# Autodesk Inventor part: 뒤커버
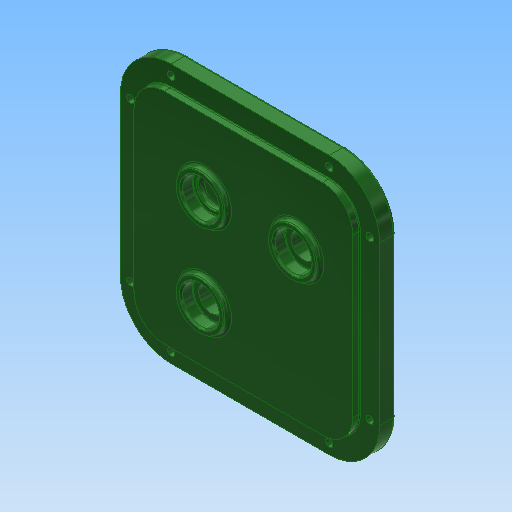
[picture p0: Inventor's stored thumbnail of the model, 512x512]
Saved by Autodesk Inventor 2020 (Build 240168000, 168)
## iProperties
Created: 2016-12
Part Number: 뒤커버
Material: 알루미늄 6061
Document SubType Name: Modeling
Designer: mduedu
Density: 2.71 g/cm^3
Mass: 786.928 g
Surface Area: 577.134 cm^2
Volume: 290.379 cm^3
Appearance: 매끄러움 - 짙은 산림 녹색
Author: mduedu
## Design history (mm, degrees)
sketch "스케치1"
  geometry: L1 (-54, 50)-(-54, -44); L2 (-24, 80)-(70, 80); L3 (100, 50)-(100, -44); L4 (70, -74)-(-24, -74); A1 r 30 centre (-24, -44) between (-54, -44) and (-24, -74); A2 r 30 centre (70, 50) between (100, 50) and (70, 80); A3 r 30 centre (70, -44) between (70, -74) and (100, -44); A4 r 30 centre (-24, 50) between (-24, 80) and (-54, 50); 1 further point
  constraints: 8 end point, 8 point on circle, 8 tangent, 4 centre point, 3 equal radius, 3 perpendicular, 1 horizontal, 1 vertical
  dimensions: "d80" = 30 radius of A2; "d81" = 154 distance between parallel lines of L4 L2; "d82" = 100 distance from line of L3 point (0, 0); "d115" = 80 distance from line of L2 point (0, 0)
extrude "돌출1" new body sketch "스케치1" distance "d3" = 14; taper "d4" = 0 deg
sketch "스케치2"
  geometry: C1 r 14 at (0, 26); 1 further point
  constraints: 1 centre point, 1 vertical alignment
  dimensions: "d5" = 28 diameter of C1; "d6" = 26 distance of C1.centre point (0, 0)
extrude "돌출2" join sketch "스케치2" distance "d7" = 3; taper "d8" = 0 deg
sketch "스케치3"
  geometry: C1 r 14 at (0, -28.87); C2 r 14 at (0, 26) reference; C3 r 14 at (54.87, 26); 1 further point
  constraints: 2 centre point, 1 horizontal alignment, 1 vertical alignment
  dimensions: "d9" = 28 diameter of C1; "d69" = 54.87 distance of C1.centre C2.centre; "d83" = 28 diameter of C3; "d84" = 54.87 distance of C3.centre C2.centre
extrude "돌출3" join sketch "스케치3" distance "d11" = 3; taper "d12" = 0 deg
hole "구멍1" diameter "d15" = 22; stored, may be unused: countersink angle "d19" = 90 deg, drill point angle "d21" = 0 deg; dims "d13" = 10, "d14" = 10, "d16" = 6, "d17" = 4, "d18" = 2, "d20" = 7
hole "구멍2" diameter "d24" = 18; stored, may be unused: countersink angle "d28" = 90 deg, drill point angle "d30" = 0 deg; dims "d25" = 6, "d26" = 4, "d27" = 2, "d29" = 3, "d119" = 10, "d120" = 10
hole "구멍3" diameter "d33" = 22; stored, may be unused: countersink angle "d37" = 90 deg, drill point angle "d39" = 0 deg; dims "d31" = 10, "d32" = 10, "d34" = 6, "d35" = 4, "d36" = 2, "d38" = 7
hole "구멍7" diameter "d87" = 22; stored, may be unused: countersink angle "d91" = 90 deg, drill point angle "d93" = 0 deg; dims "d85" = 10, "d86" = 10, "d88" = 6, "d89" = 4, "d90" = 2, "d92" = 7
sketch "스케치4"
  geometry: C1 r 14 at (0, -28.87) reference; C2 r 18 at (0, -28.87); C3 r 14 at (-54.87, 26) reference; C4 r 18 at (-54.87, 26); 1 further point
  constraints: 2 centre point, 2 coincident
  dimensions: "d40" = 36 diameter of C2; "d94" = 36 diameter of C4
extrude "돌출4" join sketch "스케치4" distance "d41" = 4; taper "d42" = 0 deg
hole "구멍4" diameter "d45" = 22; stored, may be unused: countersink angle "d49" = 90 deg, drill point angle "d51" = 0 deg; dims "d43" = 10, "d44" = 10, "d46" = 6, "d47" = 4, "d48" = 2, "d50" = 7
hole "구멍8" diameter "d97" = 22; stored, may be unused: countersink angle "d101" = 90 deg, drill point angle "d103" = 0 deg; dims "d95" = 10, "d96" = 10, "d98" = 6, "d99" = 4, "d100" = 2, "d102" = 7
hole "구멍5" diameter "d54" = 15; stored, may be unused: countersink angle "d58" = 90 deg, drill point angle "d60" = 0 deg; dims "d52" = 10, "d53" = 10, "d55" = 6, "d56" = 4, "d57" = 2, "d59" = 7
hole "구멍9" diameter "d106" = 15; stored, may be unused: countersink angle "d110" = 90 deg, drill point angle "d112" = 0 deg; dims "d104" = 10, "d105" = 10, "d107" = 6, "d108" = 4, "d109" = 2, "d111" = 7
fillet "모깎기1" dims "d61" = 0.3
fillet "모깎기2" dims "d62" = 2
chamfer "모따기1" distance "d63" = 1; stored, may be unused: second distance "d64" = 2, angle "d65" = 45 deg
fillet "모깎기3" dims "d66" = 2
fillet "모깎기4" dims "d67" = 2
fillet "모깎기5" dims "d68" = 2
sketch "스케치5"
  geometry: L1 (-70, 80)-(24, 80) reference; L2 (-100, -44)-(-100, 50) reference; L3 (24, -74)-(-70, -74) reference; L4 (54, 50)-(54, -44) reference; L5 (24, 74)-(-70, 74); L6 (-94, 50)-(-94, -44); L7 (-70, -68)-(24, -68); L8 (48, -44)-(48, 50); A1 r 30 centre (-70, 50) between (-70, 80) and (-100, 50) reference; A2 r 30 centre (-70, -44) between (-100, -44) and (-70, -74) reference; A3 r 30 centre (24, -44) between (24, -74) and (54, -44) reference; A4 r 30 centre (24, 50) between (54, 50) and (24, 80) reference; A5 r 24 centre (-70, 50) between (-70, 74) and (-94, 50); A6 r 24 centre (-70, -44) between (-94, -44) and (-70, -68); A7 r 24 centre (24, -44) between (24, -68) and (48, -44); A8 r 24 centre (24, 50) between (48, 50) and (24, 74)
  constraints: 8 end point, 8 point on circle, 4 centre point, 7 other
  dimensions: "d113" = 6 distance between parallel lines of L6 L2
sketch "스케치6"
  geometry: L1 (24, 74)-(-70, 74) reference; L2 (48, -44)-(48, 50) reference; L3 (-70, -68)-(24, -68) reference; L4 (-94, 50)-(-94, -44) reference; A1 r 24 centre (24, 50) between (48, 50) and (24, 74) reference; A2 r 24 centre (24, -44) between (24, -68) and (48, -44) reference; A3 r 24 centre (-70, -44) between (-94, -44) and (-70, -68) reference; A4 r 24 centre (-70, 50) between (-70, 74) and (-94, 50) reference; 8 further points
  constraints: 8 coincident
hole "구멍6" sketch "스케치6" at (-70, 74), (-94, 50), (-94, -44), (-70, -68), (24, -68), (48, -44), (48, 50), (24, 74) diameter "d71" = 4.5; stored, may be unused: countersink angle "d75" = 90 deg, drill point angle "d77" = 0 deg; dims "d72" = 6, "d73" = 8, "d74" = 4.6, "d76" = 8
sketch "스케치7"
  geometry: L1 (70, 80)-(-24, 80) reference; L2 (100, -44)-(100, 50) reference; L3 (-24, -74)-(70, -74) reference; L4 (-54, 50)-(-54, -44) reference; L5 (-24, 68)-(70, 68); L6 (88, 50)-(88, -44); L7 (70, -62)-(-24, -62); L8 (-42, -44)-(-42, 50); A1 r 30 centre (70, 50) between (100, 50) and (70, 80) reference; A2 r 30 centre (70, -44) between (70, -74) and (100, -44) reference; A3 r 30 centre (-24, -44) between (-54, -44) and (-24, -74) reference; A4 r 30 centre (-24, 50) between (-24, 80) and (-54, 50) reference; A5 r 18 centre (70, 50) between (88, 50) and (70, 68); A6 r 18 centre (70, -44) between (70, -62) and (88, -44); A7 r 18 centre (-24, -44) between (-42, -44) and (-24, -62); A8 r 18 centre (-24, 50) between (-24, 68) and (-42, 50); 1 further point
  constraints: 8 end point, 8 point on circle, 4 centre point, 7 other
  dimensions: "d116" = 12 distance between parallel lines of L1 L5
extrude "돌출5" cut sketch "스케치7" distance "d117" = 4; taper "d118" = 0 deg
fillet "모깎기6" dims "d121" = 0.5
node "솔리드1"
node "참조1"
node "참조2"
